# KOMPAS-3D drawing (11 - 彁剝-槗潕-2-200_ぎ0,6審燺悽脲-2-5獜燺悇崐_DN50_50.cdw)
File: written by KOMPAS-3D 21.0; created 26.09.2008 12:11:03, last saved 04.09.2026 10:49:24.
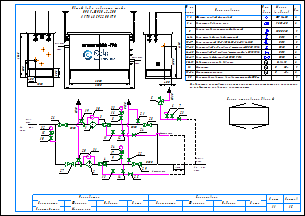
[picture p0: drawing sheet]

Sheets 1-2: A3, landscape

Document properties: Наименование: Макро:21; Автор: RaskoAdmin; Форматы листов документа: 2xA3; Полное имя файла: \\UR38nt01\Departments\КТО\КБ ПУРДГ\Заявки\Прайс-лист на типовые шкафы ГРПШ\ПРДГ_стандарт_20_03_2026\ПРДГ с РДНК\ПРДГ-ШУЭО-2-200_до0,6МПа_Рвых-2-5кПа_РДНК_DN50_50.cdw

Title block, sheet 1: Наименование: Пункт учета газа / ПУГ-Ш-400-Р / ЛГТИ.485922.001ТУ; designation: ЛГТИ.03.4411141; sheet number: 1; Количество листов документа: 2; organisation: ООО "ЭЛЬСТЕР Газэлектроника"; Форматы листов документа: A3; stored path: C:\Рабочие документы\Компас\ПУГ\Схема.cdw; Разработал: Устинов; Проверил: Кошкин; Утвердил: Кошкин
Title block, sheet 2: sheet number: 2; stored path: D:\Рабочие документы\Заявки\ПУРДГ\ПУРДГ-ШУЭО-2-100-Р 4411220.cdw; designation, second copy: ЛГТИ.03.4411141-

Views: Вид 1, Вид 2
Referenced files: wcvoit.frw
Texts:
  Normal
  Вход
  газа
  PDI
  Выход
  Р=     кПа
  DN50
  DN20
  Импульс DN15
  ≥5DN
  HYSWLongFangSong
  № на
  схеме
  Усл.
  обозн.
  Марка
  (модель)
  Кол.
  Фильтр газовый фланцевый
  ФГ 16-50
  Регулятор давления газа
  РДНК-50
  Клапан предохранительный сбросной
  КПС DN20
  Кран шаровой газовый латунный
  DN15
  Кран кнопочный VE-РАСКО-НЗ-1,6-G1/2-М20
  Кран шаровой "под приварку" штуцерный DN20 PN16
  Кран шаровой "под приварку" штуцерный п/п DN15 PN16
  Кран шаровой фланцевый DN50 PN16
  Индикатор перепада давления
  Delta 15
  Манометр
  Манометр-напоромер
  Электрообогреватель взрывозащищенный 400Вт
  0...     МПа
  0...     кПа
  Общий вид и габариты шкафа
  ПРДГ-ШУЭО-2-200
  Выход газа
  Вход газа
  Схема открывания дверей
  Р=       МПа
  logo-rasko-ge.png
  Предприятие изготовитель может заменять комплектующие на аналогичные,
  не ухудшающие заявленных характеристик.
  Должность
  Конструктор
  Фамилия
  Подпись
  Дата
  Согласовано
  Максимкин
  Лист
  Листов
  POLYLINE_STYLE_0.18_RGB_0_0_0
  POLYLINE_STYLE_0.50_RGB_0_0_0
  POLYLINE_STYLE_0.34_RGB_0_0_0
  PHANTOM_RGB_0_0_0_SC_1_THICK_0.18
  K5LT_THIN_RGB_0_0_0_THICK_0.18
  K5LT32769_RGB_0_0_0_THICK_0.18
  K5LT12_RGB_0_0_0_SC_1_THICK_0.18
  K5LT_DASHED_RGB_0_0_0_SC_1_THICK_0.18
  ACISOTGL_RGB_0_0_0_SC_0.8_THICK_0.25
  CONTINUOUS_RGB_0_127_31_THICK_0.3
  CONTINUOUS_RGB_0_0_255_THICK_0.35
  CONTINUOUS_RGB_255_0_0_THICK_0.35
  POLYLINE_STYLE_0.25_RGB_0_0_0
  CONTINUOUS_RGB_0_0_0_THICK_0.5
  POLYLINE_STYLE_0.35_RGB_0_0_255
  CONTINUOUS_RGB_0_0_0_THICK_0.4
  CONTINUOUS_RGB_0_0_0_THICK_0.35
  Без оформления
Dimensions and other numbers on the sheet: 1; 2; 3; 4; 5; 10; 27; 28; 29; 23; 8; 12; 19; 20; 21; 22; 25; 24; 30; 31; 15; 16; 26; 6; 7; 11; 14; 13; 33; 1, 2; 3, 4; 6-14; 9; 15-17; 19-23; 24-25; 26-29; 30-31; 32; 33-34; 35; 1000; 400; 1050; 500; 305; 2000; 4130; 1565; 2300; 17; 34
